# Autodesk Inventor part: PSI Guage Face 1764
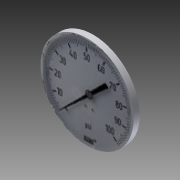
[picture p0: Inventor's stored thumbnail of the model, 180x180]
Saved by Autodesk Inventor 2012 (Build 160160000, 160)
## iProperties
Created: 2010-02
Part Number: PSI Guage Face 1764
Document SubType Name: Modeling
Designer: jgehrig
Density: 1 g/cm^3
Material: Default
Author: jgehrig
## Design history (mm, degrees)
sketch "Sketch1"
  geometry: C1 r 19.367 at (0.632, 0); 1 further point
  constraints: 1 centre point
  dimensions: "d0" = 38.735 diameter of C1
extrude "Extrusion1" new body sketch "Sketch1" distance "d1" = 2.54; taper "d2" = 0 deg
sketch "Sketch2"
  geometry: L1 (-22.667, 22.057)-(22.474, 22.057); L2 (22.474, 22.057)-(22.474, -26.304); L3 (22.474, -26.304)-(-22.667, -26.304); L4 (-22.667, -26.304)-(-22.667, 22.057); 1 further point; 1 other entity
  constraints: 2 other
feature "Decal1" sketch "Sketch2"
body "Solid1"
node "Image2"
